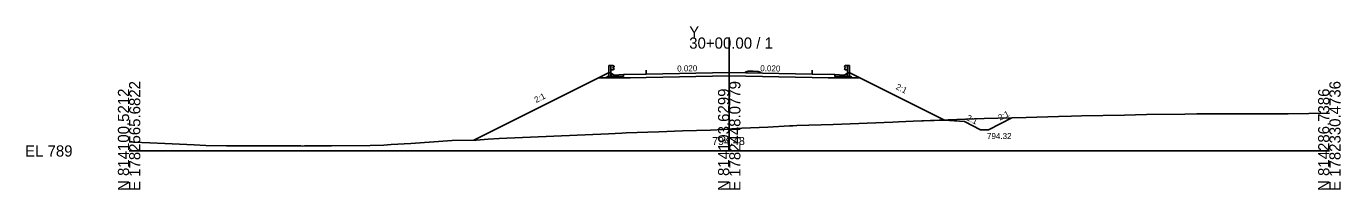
# Model space of a CAD drawing. Extents: x -12583 to 5303, y -44 to 25667.
# Drawn here: x 1974.3 to 2302.8, y 490.3 to 531.2 of the extents above; entities that cross this region are included whole.
import ezdxf

# ---------------------------------------------------------------- set-up
doc = ezdxf.new("R2010")
doc.units = 0
for name, color, linetype in [('Exist Cross Section Cell', 7, 'Continuous'), ('Exist XS Center Line Elevation Label', 7, 'Continuous'), ('Exist XS Ground Line', 7, 'Continuous'), ('Prop Conc 5in Monolithic Surface Mount Island', 7, 'Continuous'), ('Prop XS DDE', 7, 'Continuous'), ('Prop XS Ditch Standard Text', 7, 'Continuous'), ('Prop XS Dump Level', 7, 'Continuous'), ('Prop XS Earthwork Shape', 7, 'Continuous'), ('Prop XS EOT Tick Mark', 7, 'Continuous'), ('Prop XS Finish Grade', 7, 'Continuous'), ('Prop XS Finish Grade CurbGutter', 7, 'Continuous'), ('Prop XS Finish Grade Earthwork', 7, 'Continuous'), ('Prop XS Finish Grade Paved Shoulder', 7, 'Continuous'), ('Prop XS Finish Grade Pavement', 7, 'Continuous'), ('Prop XS Guardrail', 7, 'Continuous'), ('Prop XS Pvmt Edge Slope', 7, 'Continuous'), ('Prop XS SE Text', 7, 'Continuous'), ('Prop XS Side Slope Text', 7, 'Continuous'), ('Prop XS Subgrade CurbGutter', 7, 'Continuous'), ('Prop XS Subgrade Earthwork', 7, 'Continuous')]:
    doc.layers.add(name, color=color, linetype=linetype)

msp = doc.modelspace()

# ---------------------------------------------------------------- linework, layer by layer
at = {"layer": 'Exist Cross Section Cell'}
for p, q in [((2150, 500), (2150, 528.38)), ((2000, 500), (2150, 500)), ((2150, 500), (2300, 500))]:
    msp.add_line(p, q, dxfattribs=at)
at = {"layer": 'Exist XS Ground Line'}
for p, q in [((2254.27, 509.08), (2263.86, 509.23)), ((2263.86, 509.23), (2266.89, 509.26)), ((2266.89, 509.26), (2268.58, 509.28)), ((2268.58, 509.28), (2276.35, 509.28)), ((2276.35, 509.28), (2286.04, 509.29)), ((2286.04, 509.29), (2289.72, 509.31)), ((2289.72, 509.31), (2300, 509.46)), ((2153.18, 505.66), (2159.62, 505.99)), ((2159.62, 505.99), (2165.06, 506.25)), ((2165.06, 506.25), (2165.88, 506.3)), ((2165.88, 506.3), (2166.93, 506.34)), ((2166.93, 506.34), (2176, 506.62)), ((2176, 506.62), (2190.9, 507.21)), ((2190.9, 507.21), (2192.35, 507.28)), ((2192.35, 507.28), (2195.98, 507.42)), ((2195.98, 507.42), (2211.25, 508.05)), ((2211.25, 508.05), (2213.71, 508.09)), ((2213.71, 508.09), (2217.16, 508.19)), ((2217.16, 508.19), (2224.26, 508.33)), ((2224.26, 508.33), (2232.3, 508.62)), ((2232.3, 508.62), (2235.54, 508.71)), ((2235.54, 508.71), (2238.01, 508.79)), ((2238.01, 508.79), (2248.78, 508.95)), ((2248.78, 508.95), (2254.27, 509.08)), ((2080.72, 502.62), (2086.74, 502.73)), ((2086.74, 502.73), (2089.71, 502.96)), ((2089.71, 502.96), (2092.51, 503.11)), ((2092.51, 503.11), (2119.85, 504.32)), ((2119.85, 504.32), (2123.17, 504.46)), ((2123.17, 504.46), (2124.24, 504.51)), ((2124.24, 504.51), (2132.4, 504.8)), ((2132.4, 504.8), (2138.31, 505)), ((2138.31, 505), (2145.33, 505.23)), ((2145.33, 505.23), (2148.59, 505.39)), ((2148.59, 505.39), (2150, 505.48)), ((2150, 505.48), (2150.64, 505.51)), ((2150.64, 505.51), (2153.18, 505.66)), ((2000, 502.26), (2001.1, 502.24)), ((2001.1, 502.24), (2005.2, 502.05)), ((2005.2, 502.05), (2008.96, 501.88)), ((2008.96, 501.88), (2016.27, 501.51)), ((2016.27, 501.51), (2019.18, 501.36)), ((2019.18, 501.36), (2024.37, 501.28)), ((2024.37, 501.28), (2026.01, 501.3)), ((2026.01, 501.3), (2033.16, 501.31)), ((2033.16, 501.31), (2034.72, 501.26)), ((2034.72, 501.26), (2039.51, 501.26)), ((2039.51, 501.26), (2042.93, 501.26)), ((2042.93, 501.26), (2043.43, 501.24)), ((2043.43, 501.24), (2043.84, 501.27)), ((2043.84, 501.27), (2050.57, 501.29)), ((2050.57, 501.29), (2060.23, 501.35)), ((2060.23, 501.35), (2063.64, 501.48)), ((2063.64, 501.48), (2065.51, 501.58)), ((2065.51, 501.58), (2070.39, 501.87)), ((2070.39, 501.87), (2080.72, 502.62))]:
    msp.add_line(p, q, dxfattribs=at)
at = {"layer": 'Prop Conc 5in Monolithic Surface Mount Island'}
for p, q in [((2154, 519.69), (2154.76, 519.93)), ((2154, 519.53), (2154, 519.69)), ((2154.76, 519.93), (2156.01, 519.93)), ((2157.26, 519.88), (2156.01, 519.93)), ((2158, 519.61), (2157.26, 519.88)), ((2158, 519.45), (2158, 519.61))]:
    msp.add_line(p, q, dxfattribs=at)
at = {"layer": 'Prop XS DDE'}
for p, q in [((2203.77, 507.74), (2208.77, 507.33)), ((2208.77, 507.33), (2212.78, 505.32)), ((2220.66, 508.26), (2214.78, 505.32)), ((2212.78, 505.32), (2214.78, 505.32))]:
    msp.add_line(p, q, dxfattribs=at)
at = {"layer": 'Prop XS Dump Level'}
for p, q in [((2150, 519.61), (2129.25, 519.19)), ((2170.75, 519.19), (2150, 519.61))]:
    msp.add_line(p, q, dxfattribs=at)
at = {"layer": 'Prop XS Earthwork Shape'}
msp.add_lwpolyline([(2129.25, 518.4), (2125.25, 518.32), (2123.58, 518.28), (2119.19, 518.28), (2117.32, 518.28), (2086.18, 502.72), (2086.74, 502.73), (2089.71, 502.96), (2092.51, 503.11), (2119.85, 504.32), (2123.17, 504.46), (2124.24, 504.51), (2132.4, 504.8), (2138.31, 505), (2145.33, 505.23), (2148.59, 505.39), (2150, 505.48), (2150.64, 505.51), (2153.18, 505.66), (2159.62, 505.99), (2165.06, 506.25), (2165.88, 506.3), (2166.93, 506.34), (2176, 506.62), (2190.9, 507.21), (2192.35, 507.28), (2195.98, 507.42), (2203.77, 507.74), (2182.68, 518.28), (2180.81, 518.28), (2176.42, 518.28), (2174.75, 518.32), (2170.75, 518.4), (2150, 518.82)], close=True, dxfattribs=at)
at = {"layer": 'Prop XS EOT Tick Mark'}
for p, q in [((2129.25, 519.19), (2129.25, 520.19)), ((2170.75, 519.19), (2170.75, 520.19))]:
    msp.add_line(p, q, dxfattribs=at)
at = {"layer": 'Prop XS Finish Grade'}
for p, q in [((2117.32, 518.28), (2119.98, 519.62)), ((2120.56, 519.33), (2119.98, 519.62)), ((2179.44, 519.33), (2180.02, 519.62)), ((2182.68, 518.28), (2180.02, 519.62))]:
    msp.add_line(p, q, dxfattribs=at)
at = {"layer": 'Prop XS Finish Grade CurbGutter'}
for p, q in [((2121.25, 518.99), (2120.56, 519.33)), ((2178.75, 518.99), (2179.44, 519.33)), ((2123.58, 519.08), (2121.25, 518.99)), ((2176.42, 519.08), (2178.75, 518.99))]:
    msp.add_line(p, q, dxfattribs=at)
at = {"layer": 'Prop XS Finish Grade Earthwork'}
for p, q in [((2117.32, 518.28), (2086.18, 502.72)), ((2182.68, 518.28), (2203.77, 507.74))]:
    msp.add_line(p, q, dxfattribs=at)
at = {"layer": 'Prop XS Finish Grade Paved Shoulder'}
for p, q in [((2129.25, 519.19), (2123.58, 519.08)), ((2170.75, 519.19), (2176.42, 519.08))]:
    msp.add_line(p, q, dxfattribs=at)
at = {"layer": 'Prop XS Finish Grade Pavement'}
for p, q in [((2129.25, 519.19), (2150, 519.61)), ((2150, 519.61), (2129.25, 519.19)), ((2150, 519.61), (2170.75, 519.19))]:
    msp.add_line(p, q, dxfattribs=at)
at = {"layer": 'Prop XS Guardrail'}
for p, q in [((2119.93, 521.38), (2120.43, 521.38)), ((2119.93, 518.88), (2119.93, 521.38)), ((2120.43, 521.38), (2120.93, 521.38)), ((2120.43, 521.38), (2120.43, 518.88)), ((2120.93, 520.25), (2120.43, 520.25)), ((2120.93, 521.38), (2121.22, 521.18)), ((2121.22, 521.06), (2120.93, 520.86)), ((2120.93, 520.86), (2120.93, 520.77)), ((2120.93, 520.77), (2121.22, 520.57)), ((2121.22, 520.45), (2120.93, 520.25)), ((2121.22, 521.18), (2121.25, 521.12)), ((2121.25, 521.12), (2121.22, 521.06)), ((2121.22, 520.57), (2121.25, 520.51)), ((2121.25, 520.51), (2121.22, 520.45)), ((2178.78, 521.18), (2178.75, 521.12)), ((2178.75, 521.12), (2178.78, 521.06)), ((2178.78, 520.57), (2178.75, 520.51)), ((2178.75, 520.51), (2178.78, 520.45)), ((2179.07, 521.38), (2178.78, 521.18)), ((2178.78, 521.06), (2179.07, 520.86)), ((2179.07, 520.77), (2178.78, 520.57)), ((2178.78, 520.45), (2179.07, 520.25)), ((2179.57, 521.38), (2179.07, 521.38)), ((2179.07, 520.86), (2179.07, 520.77)), ((2179.07, 520.25), (2179.57, 520.25)), ((2180.07, 521.38), (2179.57, 521.38)), ((2179.57, 521.38), (2179.57, 518.88)), ((2180.07, 518.88), (2180.07, 521.38))]:
    msp.add_line(p, q, dxfattribs=at)
at = {"layer": 'Prop XS Pvmt Edge Slope'}
for p, q in [((2119.56, 518.66), (2119.19, 518.28)), ((2120.56, 518.66), (2119.56, 518.66)), ((2179.44, 518.66), (2180.44, 518.66)), ((2180.44, 518.66), (2180.81, 518.28))]:
    msp.add_line(p, q, dxfattribs=at)
at = {"layer": 'Prop XS Subgrade CurbGutter'}
for p, q in [((2120.56, 518.66), (2120.56, 519.33)), ((2179.44, 518.66), (2179.44, 519.33)), ((2123.58, 518.66), (2120.56, 518.66)), ((2123.58, 519.08), (2123.58, 518.66)), ((2176.42, 519.08), (2176.42, 518.66)), ((2176.42, 518.66), (2179.44, 518.66))]:
    msp.add_line(p, q, dxfattribs=at)
at = {"layer": 'Prop XS Subgrade Earthwork'}
for p, q in [((2119.19, 518.28), (2117.32, 518.28)), ((2123.58, 518.28), (2119.19, 518.28)), ((2125.25, 518.32), (2123.58, 518.28)), ((2129.25, 518.4), (2125.25, 518.32)), ((2150, 518.82), (2129.25, 518.4)), ((2170.75, 518.4), (2150, 518.82)), ((2170.75, 518.4), (2174.75, 518.32)), ((2174.75, 518.32), (2176.42, 518.28)), ((2176.42, 518.28), (2180.81, 518.28)), ((2180.81, 518.28), (2182.68, 518.28))]:
    msp.add_line(p, q, dxfattribs=at)

# ---------------------------------------------------------------- texts
at = {"layer": 'Exist Cross Section Cell'}
for s, p in [('Y', (2140, 528.38)), ('30+00.00 / 1', (2140, 525.58)), ('EL 789', (1974, 498.6))]:
    msp.add_text(s, height=2.8, dxfattribs=at).set_placement(p)
for s, p in [('E 1782565.6822', (2002.8, 490)), ('E 1782448.0779', (2152.8, 490)), ('E 1782330.4736', (2302.8, 490)), ('N 814100.5212', (2000, 490)), ('N 814193.6299', (2150, 490)), ('N 814286.7386', (2300, 490))]:
    msp.add_text(s, height=2.8, rotation=90, dxfattribs=at).set_placement(p)
at = {"layer": 'Exist XS Center Line Elevation Label'}
msp.add_text('794.48', height=2, dxfattribs=at).set_placement((2145.73, 501.48))
at = {"layer": 'Prop XS Ditch Standard Text'}
msp.add_text('794.32', height=1.5, dxfattribs=at).set_placement((2214.43, 502.98))
at = {"layer": 'Prop XS Dump Level'}
msp.add_text('Case2', height=0.04, dxfattribs=at).set_placement((2176.42, 519.04))
at = {"layer": 'Prop XS SE Text'}
for rotation, p in [(1.1458, (2137, 519.85)), (1.1458, (2137, 519.85)), (358.8542, (2157.75, 519.95))]:
    msp.add_text('0.020', height=1.5, rotation=rotation, dxfattribs=at).set_placement(p)
at = {"layer": 'Prop XS Side Slope Text'}
for rotation, p in [(333.4349, (2191.5, 515.55)), (26.5651, (2101.75, 511.98)), (26.5651, (2217.67, 507.56)), (333.4349, (2209.14, 507.82))]:
    msp.add_text('2:1', height=1.5, rotation=rotation, dxfattribs=at).set_placement(p)

doc.saveas('drawing.dxf')
